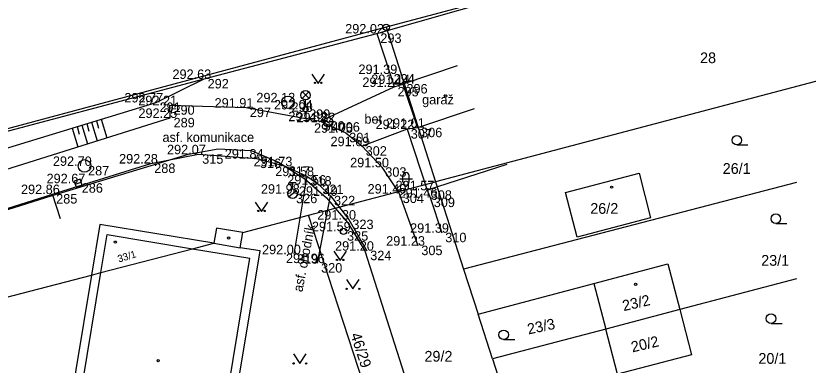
# Model space of a CAD drawing. Extents: x -599866 to -590076, y -1178039 to -1154526.
# Drawn here: x -599754.4 to -599691.8, y -1154686.6 to -1154658.9 of the extents above; entities that cross this region are included whole.
import ezdxf

# ---------------------------------------------------------------- set-up
doc = ezdxf.new("R2010")
doc.units = 0
for name, color, linetype in [('Budovy', 7, 'Continuous'), ('IS neurčené', 7, 'Continuous'), ('IS plyn', 7, 'Continuous'), ('IS vodovod', 7, 'Continuous'), ('KN', 7, 'Continuous'), ('Ploty', 7, 'Continuous'), ('Popisy', 7, 'Continuous'), ('Rozhraní ploch', 7, 'Continuous'), ('Vjezdy', 7, 'Continuous'), ('VO rozhlas', 7, 'Continuous'), ('Vrstva 54', 7, 'Continuous'), ('Vrstva 55', 7, 'Continuous'), ('Vrstva 56', 7, 'Continuous'), ('Vrstva 58', 7, 'Continuous'), ('Vrstva 59', 7, 'Continuous'), ('Vrstva 60', 7, 'Continuous'), ('Výškopis', 7, 'Continuous'), ('Značky budov', 7, 'Continuous'), ('Značky kultur', 7, 'Continuous')]:
    doc.layers.add(name, color=color, linetype=linetype)

msp = doc.modelspace()

# ---------------------------------------------------------------- linework, layer by layer
at = {"layer": 'Budovy'}
for p, q in [((-599719.582, -1154662.906), (-599723.86, -1154664.34)), ((-599718.214, -1154666.296), (-599722.7, -1154667.8))]:
    msp.add_line(p, q, dxfattribs=at)
msp.add_lwpolyline([(-599723.86, -1154664.34), (-599722.7, -1154667.8)], dxfattribs=at)
at = {"layer": 'IS neurčené'}
msp.add_line((-599749.757, -1154672.269), (-599749.283, -1154672.111), dxfattribs=at)
msp.add_lwpolyline([(-599749.678, -1154672.506), (-599749.204, -1154672.348), (-599749.362, -1154671.874), (-599749.836, -1154672.032)], close=True, dxfattribs=at)
for centre in [(-599732.94, -1154665.79), (-599749.02, -1154670.82)]:
    msp.add_circle(centre, 0.5, dxfattribs=at)
at = {"layer": 'IS plyn'}
msp.add_circle((-599728.55, -1154675.99), 0.25, dxfattribs=at)
at = {"layer": 'IS vodovod'}
for p, q in [((-599732.83, -1154672.144), (-599732.33, -1154672.144)), ((-599732.58, -1154672.644), (-599732.58, -1154672.144)), ((-599732.874, -1154673.252), (-599732.284, -1154672.788))]:
    msp.add_line(p, q, dxfattribs=at)
msp.add_circle((-599732.58, -1154673.02), 0.375, dxfattribs=at)
at = {"layer": 'KN'}
for p, q in [((-599685.27, -1154649.13), (-599725.18, -1154659.85)), ((-599725.18, -1154659.85), (-599770.56, -1154672.04)), ((-599725.18, -1154659.85), (-599721.27, -1154672.07)), ((-599683.62, -1154662.13), (-599721.27, -1154672.07)), ((-599697.466, -1154669.16), (-599696.591, -1154669.16)), ((-599729.2, -1154674.16), (-599721.27, -1154672.07)), ((-599721.27, -1154672.07), (-599719.06, -1154678.98)), ((-599692.76, -1154672.124), (-599719.06, -1154678.98)), ((-599729.9, -1154673.34), (-599729.2, -1154674.16)), ((-599731.32, -1154674.72), (-599729.2, -1154674.16)), ((-599729.2, -1154674.16), (-599728.2, -1154675.33)), ((-599736.51, -1154676.1), (-599731.32, -1154674.72)), ((-599724.53, -1154695.57), (-599731.32, -1154674.72)), ((-599728.2, -1154675.33), (-599726.87, -1154677.54)), ((-599694.387, -1154675.37), (-599693.512, -1154675.37)), ((-599747.72, -1154679.26), (-599747.22, -1154676.26)), ((-599747.22, -1154676.26), (-599740.48, -1154677.38)), ((-599736.71, -1154677.29), (-599736.51, -1154676.1)), ((-599738.79, -1154676.94), (-599736.71, -1154677.29)), ((-599740.48, -1154677.38), (-599735.95, -1154678.13)), ((-599739.18, -1154697.59), (-599735.95, -1154678.13)), ((-599750.37, -1154695.25), (-599747.72, -1154679.26)), ((-599719.06, -1154678.98), (-599717.92, -1154682.54)), ((-599717.92, -1154682.54), (-599708.78, -1154680.13)), ((-599708.78, -1154680.13), (-599707.83, -1154683.73)), ((-599692.76, -1154679.764), (-599701.97, -1154682.19)), ((-599716.78, -1154686.08), (-599717.92, -1154682.54)), ((-599701.97, -1154682.19), (-599707.83, -1154683.73)), ((-599694.767, -1154683.28), (-599693.892, -1154683.28)), ((-599707.83, -1154683.73), (-599716.78, -1154686.08)), ((-599715.897, -1154684.56), (-599715.022, -1154684.56)), ((-599716.78, -1154686.08), (-599714.57, -1154692.99))]:
    msp.add_line(p, q, dxfattribs=at)
for points in [[(-599806.74, -1154690.566), (-599751.66, -1154673.18), (-599740.79, -1154669.9), (-599738.46, -1154669.48), (-599735.86, -1154669.61), (-599733.7, -1154670.53), (-599731.62, -1154671.85), (-599729.9, -1154673.34)], [(-599711.01, -1154672.93), (-599705.18, -1154671.39), (-599704.28, -1154674.93), (-599710.08, -1154676.46), (-599711.01, -1154672.93)], [(-599738.79, -1154676.94), (-599747.8, -1154675.45), (-599748.46, -1154679.46)], [(-599736.51, -1154676.1), (-599738.6, -1154675.75), (-599738.79, -1154676.94)], [(-599748.46, -1154679.46), (-599747.72, -1154679.26), (-599740.48, -1154677.38), (-599738.79, -1154676.94)], [(-599738.49, -1154697.7), (-599735.14, -1154677.55), (-599736.71, -1154677.29)], [(-599726.87, -1154677.54), (-599722.78, -1154690.35), (-599724.39, -1154690.82), (-599723.03, -1154695.18)], [(-599708.78, -1154680.13), (-599702.91, -1154678.58), (-599701.97, -1154682.19)], [(-599783.66, -1154688.71), (-599773.98, -1154686.09), (-599748.46, -1154679.46)], [(-599748.46, -1154679.46), (-599750.95, -1154694.45), (-599751.79, -1154694.31), (-599752.01, -1154695.61)], [(-599728.31, -1154679.799), (-599727.81, -1154680.55), (-599727.31, -1154679.799)], [(-599701.97, -1154682.19), (-599701.05, -1154685.76), (-599706.9, -1154687.29), (-599707.83, -1154683.73)], [(-599732.5, -1154685.7), (-599732, -1154686.45), (-599731.5, -1154685.7)]]:
    msp.add_lwpolyline(points, dxfattribs=at)
for centre, radius in [((-599725.18, -1154659.85), 0.25), ((-599725.18, -1154659.85), 0.0152), ((-599697.466, -1154668.785), 0.375), ((-599707.363, -1154672.5), 0.0875), ((-599694.386, -1154674.995), 0.375), ((-599746.583, -1154676.85), 0.0875), ((-599737.633, -1154676.53), 0.0875), ((-599705.463, -1154680.19), 0.0875), ((-599728.31, -1154680.55), 0.05), ((-599727.31, -1154680.55), 0.05), ((-599694.766, -1154682.905), 0.375), ((-599715.896, -1154684.185), 0.375), ((-599743.203, -1154686.23), 0.0875), ((-599732.5, -1154686.45), 0.05), ((-599731.5, -1154686.45), 0.05)]:
    msp.add_circle(centre, radius, dxfattribs=at)
at = {"layer": 'Ploty'}
msp.add_line((-599715.651, -1154670.697), (-599721.94, -1154672.75), dxfattribs=at)
for points in [[(-599773.96, -1154673.2), (-599770.5, -1154672.18), (-599759, -1154669.11), (-599739.57, -1154663.94), (-599725.92, -1154660.34), (-599716.21, -1154657.55), (-599712.3, -1154656.54)], [(-599725.92, -1154660.34), (-599724.87, -1154663.55)], [(-599724.56, -1154664.57), (-599723.86, -1154664.34)], [(-599722.7, -1154667.8), (-599723.52, -1154667.91), (-599721.94, -1154672.75), (-599721.7, -1154673.33)]]:
    msp.add_lwpolyline(points, dxfattribs=at)
at = {"layer": 'Rozhraní ploch'}
msp.add_line((-599750.924, -1154675.001), (-599751.54, -1154673.05), dxfattribs=at)
for points in [[(-599730.41, -1154667.28), (-599724.56, -1154664.57)], [(-599772.56, -1154676.51), (-599759.45, -1154672.41), (-599742.26, -1154667.02), (-599742.27, -1154666.02), (-599736.24, -1154666.21), (-599730.41, -1154667.28), (-599728.38, -1154668.2), (-599727.08, -1154669.26), (-599725.53, -1154670.93), (-599724.15, -1154673.01), (-599722.68, -1154677.13)], [(-599723.52, -1154667.91), (-599727.08, -1154669.26)], [(-599758.73, -1154675.32), (-599751.54, -1154673.05), (-599743.79, -1154670.63), (-599740, -1154669.9), (-599735.44, -1154670.24), (-599733.16, -1154670.85), (-599731.45, -1154671.63), (-599730.5, -1154672.3), (-599729.58, -1154673.19), (-599728.13, -1154675.07), (-599726.72, -1154677.53)], [(-599731.45, -1154671.63), (-599732.49, -1154677.81)], [(-599730.6, -1154678.51), (-599729.58, -1154673.19)]]:
    msp.add_lwpolyline(points, dxfattribs=at)
at = {"layer": 'Vjezdy'}
for points in [[(-599724.87, -1154663.55), (-599724.56, -1154664.57)], [(-599721.7, -1154673.33), (-599720.79, -1154676.11)]]:
    msp.add_lwpolyline(points, dxfattribs=at)
at = {"layer": 'VO rozhlas'}
for p, q in [((-599731.814, -1154665.488), (-599731.286, -1154664.96)), ((-599731.278, -1154665.486), (-599731.806, -1154664.956)), ((-599731.55, -1154666.15), (-599731.55, -1154665.6))]:
    msp.add_line(p, q, dxfattribs=at)
for centre, radius in [((-599731.55, -1154665.225), 0.375), ((-599731.55, -1154666.35), 0.2)]:
    msp.add_circle(centre, radius, dxfattribs=at)
at = {"layer": 'Vrstva 56'}
for radius in [0.375, 0.375, 0.0179, 0.0179]:
    msp.add_circle((-599729.77, -1154667.36), radius, dxfattribs=at)
at = {"layer": 'Vrstva 60'}
for p, q in [((-599725.92, -1154660.34), (-599725.92, -1154660.34)), ((-599724.87, -1154663.55), (-599724.87, -1154663.55)), ((-599739.57, -1154663.94), (-599739.57, -1154663.94)), ((-599723.86, -1154664.34), (-599723.86, -1154664.34)), ((-599724.56, -1154664.57), (-599724.56, -1154664.57)), ((-599743.37, -1154665.8), (-599743.37, -1154665.8)), ((-599742.27, -1154666.02), (-599742.27, -1154666.02)), ((-599736.24, -1154666.21), (-599736.24, -1154666.21)), ((-599732.94, -1154665.79), (-599732.94, -1154665.79)), ((-599731.55, -1154666.35), (-599731.55, -1154666.35)), ((-599742.26, -1154667.02), (-599742.26, -1154667.02)), ((-599730.41, -1154667.28), (-599730.41, -1154667.28)), ((-599728.38, -1154668.2), (-599728.38, -1154668.2)), ((-599723.52, -1154667.91), (-599723.52, -1154667.91)), ((-599722.7, -1154667.8), (-599722.7, -1154667.8)), ((-599727.08, -1154669.26), (-599727.08, -1154669.26)), ((-599740, -1154669.9), (-599740, -1154669.9)), ((-599743.79, -1154670.63), (-599743.79, -1154670.63)), ((-599735.44, -1154670.24), (-599735.44, -1154670.24)), ((-599749.02, -1154670.82), (-599749.02, -1154670.82)), ((-599733.16, -1154670.85), (-599733.16, -1154670.85)), ((-599725.53, -1154670.93), (-599725.53, -1154670.93)), ((-599731.45, -1154671.63), (-599731.45, -1154671.63)), ((-599749.52, -1154672.19), (-599749.52, -1154672.19)), ((-599730.5, -1154672.3), (-599730.5, -1154672.3)), ((-599751.54, -1154673.05), (-599751.54, -1154673.05)), ((-599732.58, -1154673.02), (-599732.58, -1154673.02)), ((-599729.58, -1154673.19), (-599729.58, -1154673.19)), ((-599724.15, -1154673.01), (-599724.15, -1154673.01)), ((-599721.94, -1154672.75), (-599721.94, -1154672.75)), ((-599721.7, -1154673.33), (-599721.7, -1154673.33)), ((-599728.13, -1154675.07), (-599728.13, -1154675.07)), ((-599728.55, -1154675.99), (-599728.55, -1154675.99)), ((-599720.79, -1154676.11), (-599720.79, -1154676.11)), ((-599726.72, -1154677.53), (-599726.72, -1154677.53)), ((-599722.68, -1154677.13), (-599722.68, -1154677.13)), ((-599732.49, -1154677.81), (-599732.49, -1154677.81)), ((-599730.6, -1154678.51), (-599730.6, -1154678.51))]:
    msp.add_line(p, q, dxfattribs=at)
at = {"layer": 'Výškopis'}
for p, q in [((-599749.232, -1154667.592), (-599748.781, -1154669.065)), ((-599748.849, -1154667.475), (-599748.669, -1154668.063)), ((-599748.467, -1154667.358), (-599748.018, -1154668.825)), ((-599748.084, -1154667.241), (-599747.905, -1154667.827)), ((-599747.702, -1154667.124), (-599747.255, -1154668.586)), ((-599749.997, -1154667.826), (-599749.545, -1154669.304)), ((-599749.614, -1154667.709), (-599749.434, -1154668.299))]:
    msp.add_line(p, q, dxfattribs=at)
for points in [[(-599743.37, -1154665.8), (-599739.57, -1154663.94)], [(-599771.85, -1154674.75), (-599759.76, -1154670.81), (-599743.37, -1154665.8)]]:
    msp.add_lwpolyline(points, dxfattribs=at)
at = {"layer": 'Značky budov'}
msp.add_circle((-599720.47, -1154665.29), 0.0875, dxfattribs=at)
at = {"layer": 'Značky kultur'}
for p, q in [((-599724.11, -1154671.84), (-599723.11, -1154671.84)), ((-599723.86, -1154672.09), (-599723.86, -1154671.59)), ((-599723.36, -1154672.09), (-599723.36, -1154671.59))]:
    msp.add_line(p, q, dxfattribs=at)
for points in [[(-599731.05, -1154663.55), (-599730.55, -1154664.3), (-599730.05, -1154663.55)], [(-599735.54, -1154673.68), (-599735.04, -1154674.43), (-599734.54, -1154673.68)], [(-599729.32, -1154677.56), (-599728.82, -1154678.31), (-599728.32, -1154677.56)]]:
    msp.add_lwpolyline(points, dxfattribs=at)
for centre in [(-599730.8, -1154664.25), (-599730.3, -1154664.25), (-599735.29, -1154674.38), (-599734.79, -1154674.38), (-599729.07, -1154678.26), (-599728.57, -1154678.26)]:
    msp.add_circle(centre, 0.05, dxfattribs=at)
for centre, start, end in [((-599723.61, -1154671.59), 0, 179.99999), ((-599723.61, -1154672.09), 179.99999, 359.99999)]:
    msp.add_arc(centre, 0.25, start, end, dxfattribs=at)

# ---------------------------------------------------------------- texts
at = {"layer": 'KN'}
for s, p in [('28', (-599700.373, -1154662.69)), ('26/1', (-599698.583, -1154671.45)), ('26/2', (-599709.053, -1154674.612)), ('23/1', (-599695.543, -1154678.72)), ('29/2', (-599722.155, -1154686.31)), ('20/1', (-599695.763, -1154686.48))]:
    msp.add_text(s, height=0.85, dxfattribs=at).set_placement(p)
for s, height, rotation, p in [('33/1', 0.57, 17, (-599746.308, -1154678.468)), ('23/2', 0.85, 13, (-599706.409, -1154682.318)), ('23/3', 0.85, 12, (-599713.933, -1154684.161)), ('46/29', 0.85, 288, (-599728.013, -1154684.173)), ('20/2', 0.85, 13, (-599705.717, -1154685.579))]:
    msp.add_text(s, height=height, rotation=rotation, dxfattribs=at).set_placement(p)
at = {"layer": 'Popisy'}
for s, p in [('garáž', (-599722.34, -1154665.95)), ('bet.', (-599726.9, -1154667.48)), ('asf. komunikace', (-599742.86, -1154668.93))]:
    msp.add_text(s, height=0.75, dxfattribs=at).set_placement(p)
msp.add_text('asf. chodník', height=0.75, rotation=79.14643, dxfattribs=at).set_placement((-599731.807, -1154680.833))
at = {"layer": 'Vrstva 54'}
msp.add_text('291.82 ', height=0.75, dxfattribs=at).set_placement((-599732.27, -1154667.36))
at = {"layer": 'Vrstva 55'}
msp.add_text(' 4006', height=0.75, dxfattribs=at).set_placement((-599729.77, -1154668.11))
at = {"layer": 'Vrstva 58'}
for s, p in [('292.02 ', (-599728.42, -1154660.34)), ('292.63 ', (-599742.07, -1154663.94)), ('291.39 ', (-599727.37, -1154663.55)), ('291.24 ', (-599727.06, -1154664.57)), ('291.14 ', (-599726.36, -1154664.34)), ('292.77 ', (-599745.87, -1154665.8)), ('292.12 ', (-599735.44, -1154665.79)), ('292.21 ', (-599744.77, -1154666.02)), ('291.91 ', (-599738.74, -1154666.21)), ('292.04 ', (-599734.05, -1154666.35)), ('292.25 ', (-599744.76, -1154667.02)), ('291.82 ', (-599732.91, -1154667.28)), ('291.75 ', (-599730.88, -1154668.2)), ('291.22 ', (-599726.02, -1154667.91)), ('291.01 ', (-599725.2, -1154667.8)), ('291.69 ', (-599729.58, -1154669.26)), ('292.07 ', (-599742.5, -1154669.9)), ('291.84 ', (-599737.94, -1154670.24)), ('292.70 ', (-599751.52, -1154670.82)), ('292.28 ', (-599746.29, -1154670.63)), ('291.73 ', (-599735.66, -1154670.85)), ('291.50 ', (-599728.03, -1154670.93)), ('291.58 ', (-599733.95, -1154671.63)), ('292.67 ', (-599752.02, -1154672.19)), ('291.56 ', (-599733, -1154672.3)), ('291.57 ', (-599724.44, -1154672.75)), ('292.86 ', (-599754.04, -1154673.05)), ('291.98 ', (-599735.08, -1154673.02)), ('291.49 ', (-599732.08, -1154673.19)), ('291.40 ', (-599726.65, -1154673.01)), ('291.46 ', (-599724.2, -1154673.33)), ('291.30 ', (-599730.63, -1154675.07)), ('291.59 ', (-599731.05, -1154675.99)), ('291.39 ', (-599723.29, -1154676.11)), ('291.23 ', (-599725.18, -1154677.13)), ('291.20 ', (-599729.22, -1154677.53)), ('292.00 ', (-599734.99, -1154677.81)), ('291.96 ', (-599733.1, -1154678.51))]:
    msp.add_text(s, height=0.75, dxfattribs=at).set_placement(p)
at = {"layer": 'Vrstva 59'}
for s, p in [(' 293', (-599725.92, -1154661.09)), (' 294', (-599724.87, -1154664.3)), (' 292', (-599739.57, -1154664.69)), (' 296', (-599723.86, -1154665.09)), (' 295', (-599724.56, -1154665.32)), (' 291', (-599743.37, -1154666.55)), (' 290', (-599742.27, -1154666.77)), (' 297', (-599736.24, -1154666.96)), (' 298', (-599732.94, -1154666.54)), (' 299', (-599731.55, -1154667.1)), (' 289', (-599742.26, -1154667.77)), (' 300', (-599730.41, -1154668.03)), (' 301', (-599728.38, -1154668.95)), (' 307', (-599723.52, -1154668.66)), (' 306', (-599722.7, -1154668.55)), (' 302', (-599727.08, -1154670.01)), (' 315', (-599740, -1154670.65)), (' 288', (-599743.79, -1154671.38)), (' 316', (-599735.44, -1154670.99)), (' 287', (-599749.02, -1154671.57)), (' 317', (-599733.16, -1154671.6)), (' 303', (-599725.53, -1154671.68)), (' 318', (-599731.45, -1154672.38)), (' 286', (-599749.52, -1154672.94)), (' 321', (-599730.5, -1154673.05)), (' 285', (-599751.54, -1154673.8)), (' 326', (-599732.58, -1154673.77)), (' 322', (-599729.58, -1154673.94)), (' 304', (-599724.15, -1154673.76)), (' 308', (-599721.94, -1154673.5)), (' 309', (-599721.7, -1154674.08)), (' 323', (-599728.13, -1154675.82)), (' 325', (-599728.55, -1154676.74)), (' 310', (-599720.79, -1154676.86)), (' 324', (-599726.72, -1154678.28)), (' 305', (-599722.68, -1154677.88)), (' 319', (-599732.49, -1154678.56)), (' 320', (-599730.6, -1154679.26))]:
    msp.add_text(s, height=0.75, dxfattribs=at).set_placement(p)

doc.saveas('drawing.dxf')
